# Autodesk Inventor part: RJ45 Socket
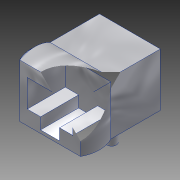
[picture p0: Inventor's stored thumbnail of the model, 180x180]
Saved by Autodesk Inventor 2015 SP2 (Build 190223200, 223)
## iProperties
Created: 2014-11
Part Number: RJ45 Socket
Material: Aluminium 6061
Document SubType Name: Modeling
Designer: AndreR
Mass: 10.7449 g
Surface Area: 22.49 cm^2
Volume: 3.96489 cm^3
Density: 2.71 g/cm^3
Appearance: Aluminium - flach
Author: AndreR
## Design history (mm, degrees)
sketch "Skizze1"
  geometry: L1 (-8, 10.5)-(8, 10.5); L2 (8, 10.5)-(8, -10.5); L3 (8, -10.5)-(-8, -10.5); L4 (-8, -10.5)-(-8, 10.5); L5 (0, 14.7)-(0, -14.7) reference; L6 (-11.2, 0)-(11.2, 0) reference; 1 further point
  constraints: 8 end point, 2 parallel, 1 horizontal, 1 perpendicular, 2 other
  dimensions: "d0" = 16 distance of L1.start L1.end; "d2" = 21 distance of L3.end L1.start
extrude "Extrusion1" new body sketch "Skizze1" distance "d3" = 14; taper "d4" = 0 deg
sketch "Skizze2"
  geometry: L1 (2, 11)-(14, 11); L2 (14, 11)-(14, 3.8); L3 (2, 3.8)-(2, 11); L4 (10.5, 3.8)-(10.5, 0.8); L5 (10.5, 0.8)-(5.5, 0.8); L6 (5.5, 0.8)-(5.5, 3.8); L7 (16, 0)-(0, 0) reference; L8 (16, 0)-(16, 14) reference; L9 (0, 14)-(16, 14) reference; L10 (0, 0)-(0, 14) reference; L11 (8, 14)-(8, 0); L12 (14, 3.8)-(10.5, 3.8); L13 (5.5, 3.8)-(2, 3.8)
  constraints: 18 end point, 4 parallel, 2 perpendicular, 1 horizontal, 1 midpoint, 3 other
  dimensions: "d5" = 3 distance between parallel lines of L1 L9; "d6" = 0.8 distance between parallel lines of L5 L7; "d8" = 2 distance between parallel lines of L2 L8; "d9" = 5 distance of L4.end L5.end; "d10" = 3 distance between parallel lines of L5 L12
extrude "Extrusion2" cut sketch "Skizze2" distance "d11" = 10; taper "d12" = 0 deg
sketch "Skizze3"
  geometry: L1 (-8, -10.5)-(8, -10.5) reference; L2 (-8, 10.5)-(-8, -10.5) reference; L3 (8, -10.5)-(8, 10.5) reference; L4 (-5.7, 0)-(5.7, 0); L5 (0, -14.7)-(0, 14.7) reference; C1 r 1.5 at (-5.7, 0); C2 r 1.5 at (5.7, 0); 1 further point
  constraints: 2 centre point, 2 coincident, 2 end point, 1 perpendicular, 1 symmetric about line
  dimensions: "d13" = 10.5 distance between parallel lines of L1 L4; "d14" = 11.4 distance of L4.end L4.start; "d15" = 3 diameter of C1; "d16" = 3 diameter of C2
extrude "Extrusion3" join sketch "Skizze3" distance "d17" = 3.2; taper "d18" = -5 deg
sketch "Skizze4"
  geometry: L1 (14, 21)-(14, 0) reference; L2 (14, 0)-(14, 8); A1 r 8.5 centre (6.5, 4) between (14, 0) and (14, 8); 1 further point
  constraints: 2 end point, 2 point on circle, 1 centre point, 1 collinear, 1 point on line
  dimensions: "d19" = 1 distance edge to line of A1 L1; "d20" = 8 distance of L2.end L1.end
extrude "Extrusion4" join sketch "Skizze4" distance "d21" = 16; taper "d22" = 0 deg
sketch "Skizze5"
  geometry: L1 (-8, 10.5)-(-8, -10.5) reference; L2 (8, -10.5)-(8, 10.5) reference; L3 (-8, -10.5)-(-8, -2.5); A1 r 8.5 centre (-0.5, -6.5) between (-8, -2.5) and (-8, -10.5); 1 further point
  constraints: 2 end point, 2 point on circle, 1 centre point, 1 collinear, 1 point on line
  dimensions: "d23" = 1 distance edge to line of A1 L1; "d24" = 8 distance of L3.end L1.end
extrude "Extrusion5" join sketch "Skizze5" distance "d25" = 14; taper "d26" = 0 deg
mirror "Spiegeln1"
node "Volumenkörper1"
node "Projizierte Kontur1"
